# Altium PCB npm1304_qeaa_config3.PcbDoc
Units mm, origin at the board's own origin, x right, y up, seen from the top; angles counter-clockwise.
Board outline 16.75 x 14 mm, 4 copper layers (Top Layer, Mid-Layer 1, Mid-Layer 2, Bottom Layer), stack 1.592 mm thick; 8 components, 15 nets, 47 pads, 52 vias.
Unrouted connection lines stored in the file: 20.
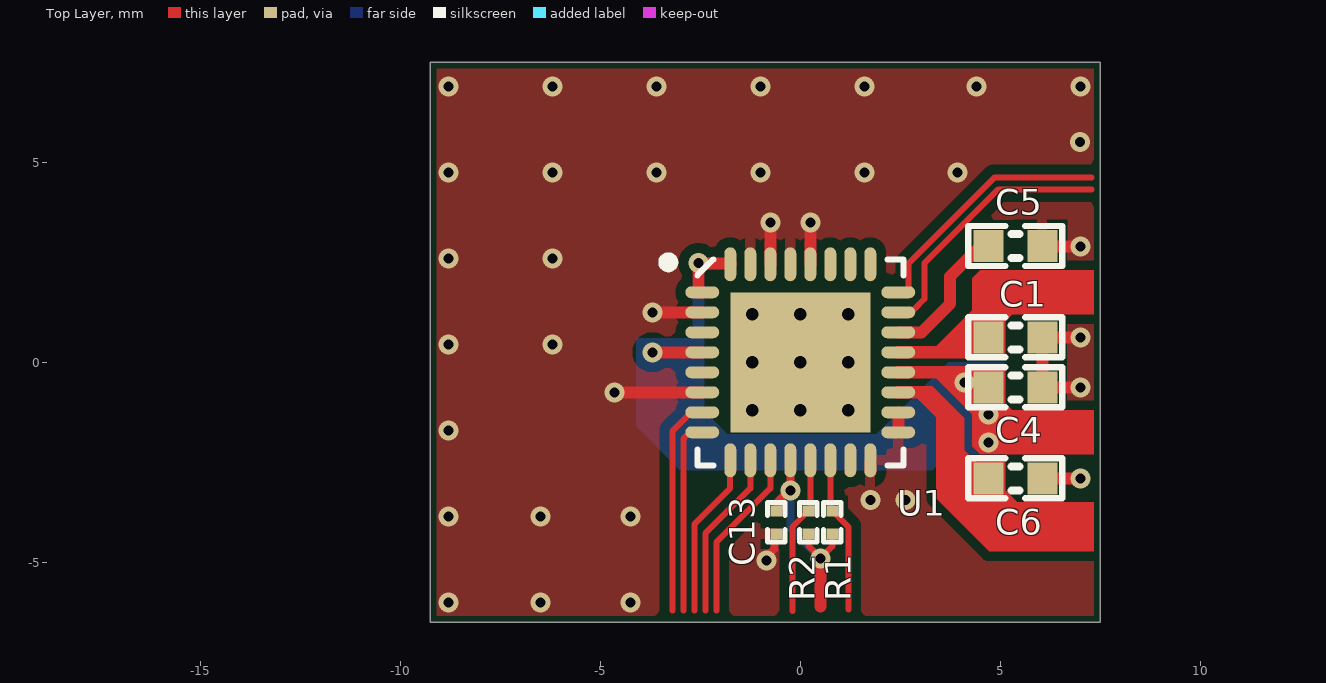
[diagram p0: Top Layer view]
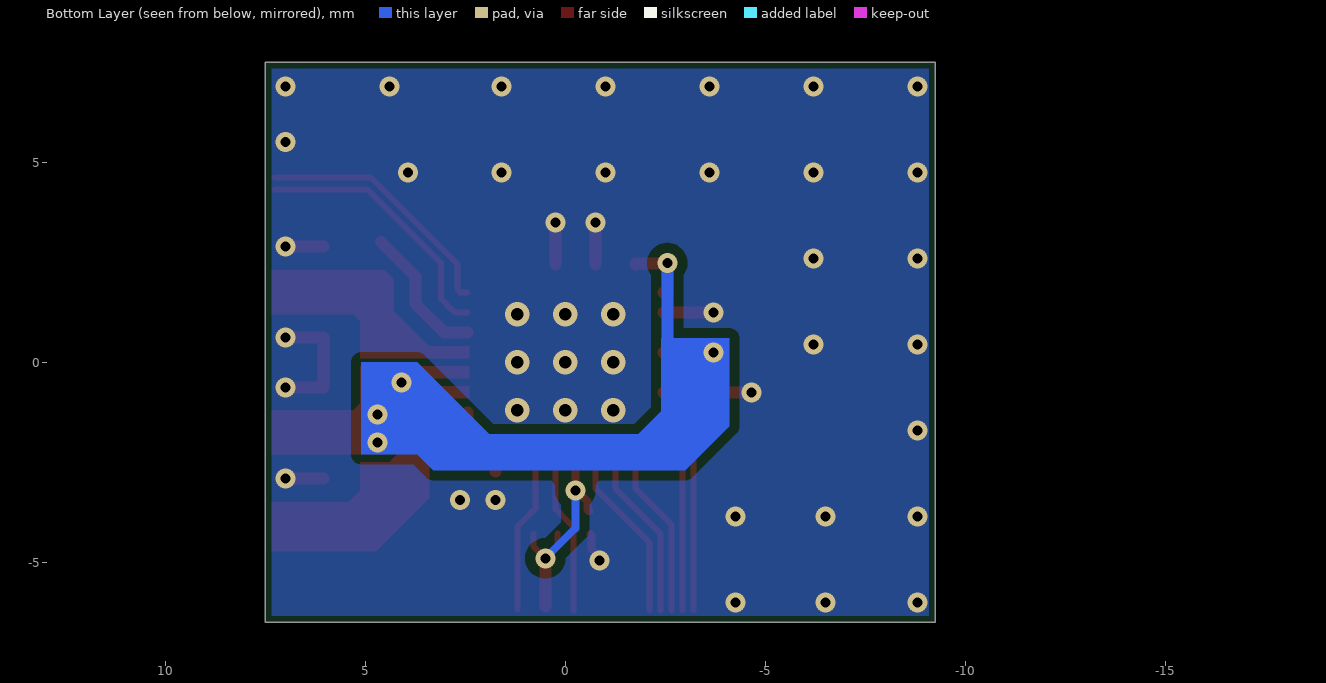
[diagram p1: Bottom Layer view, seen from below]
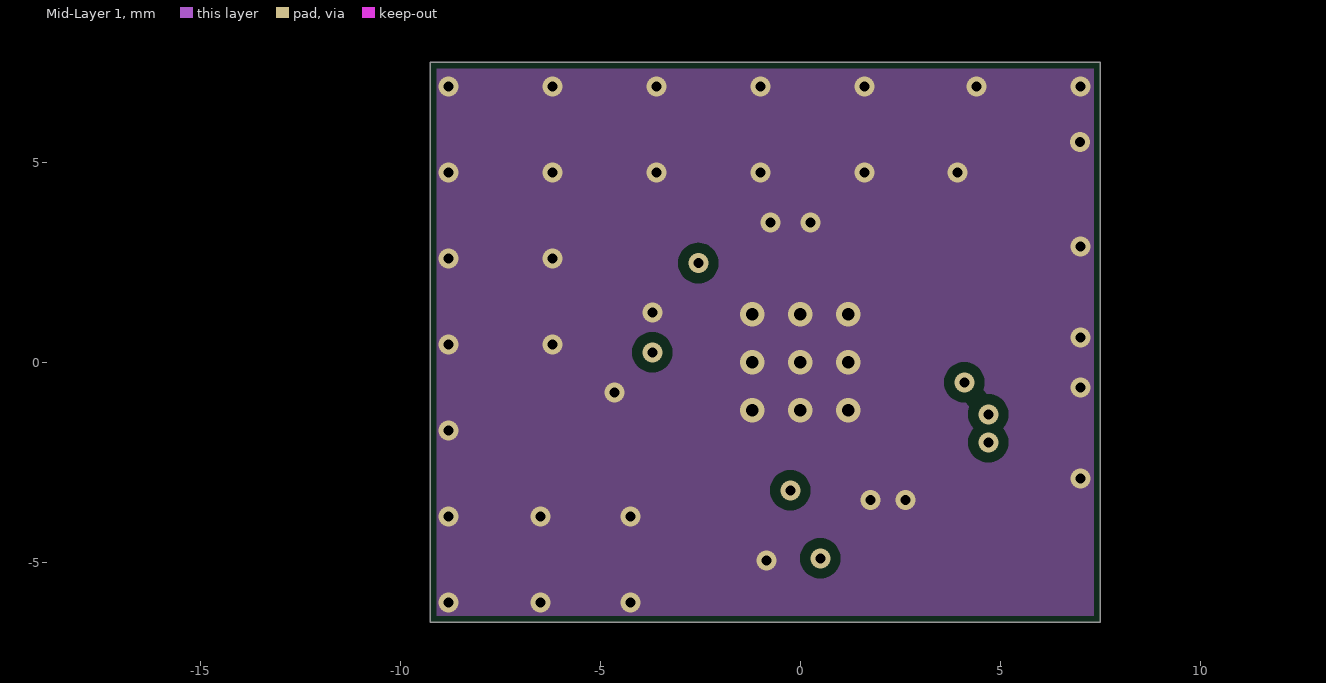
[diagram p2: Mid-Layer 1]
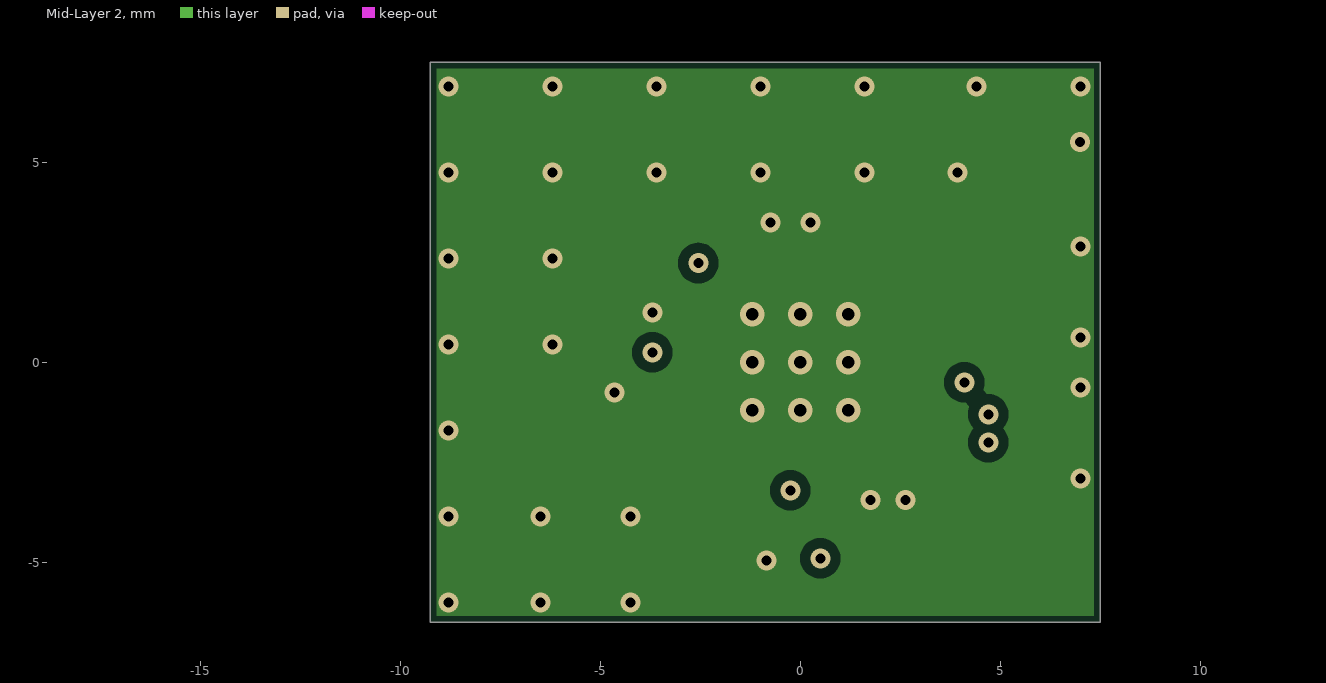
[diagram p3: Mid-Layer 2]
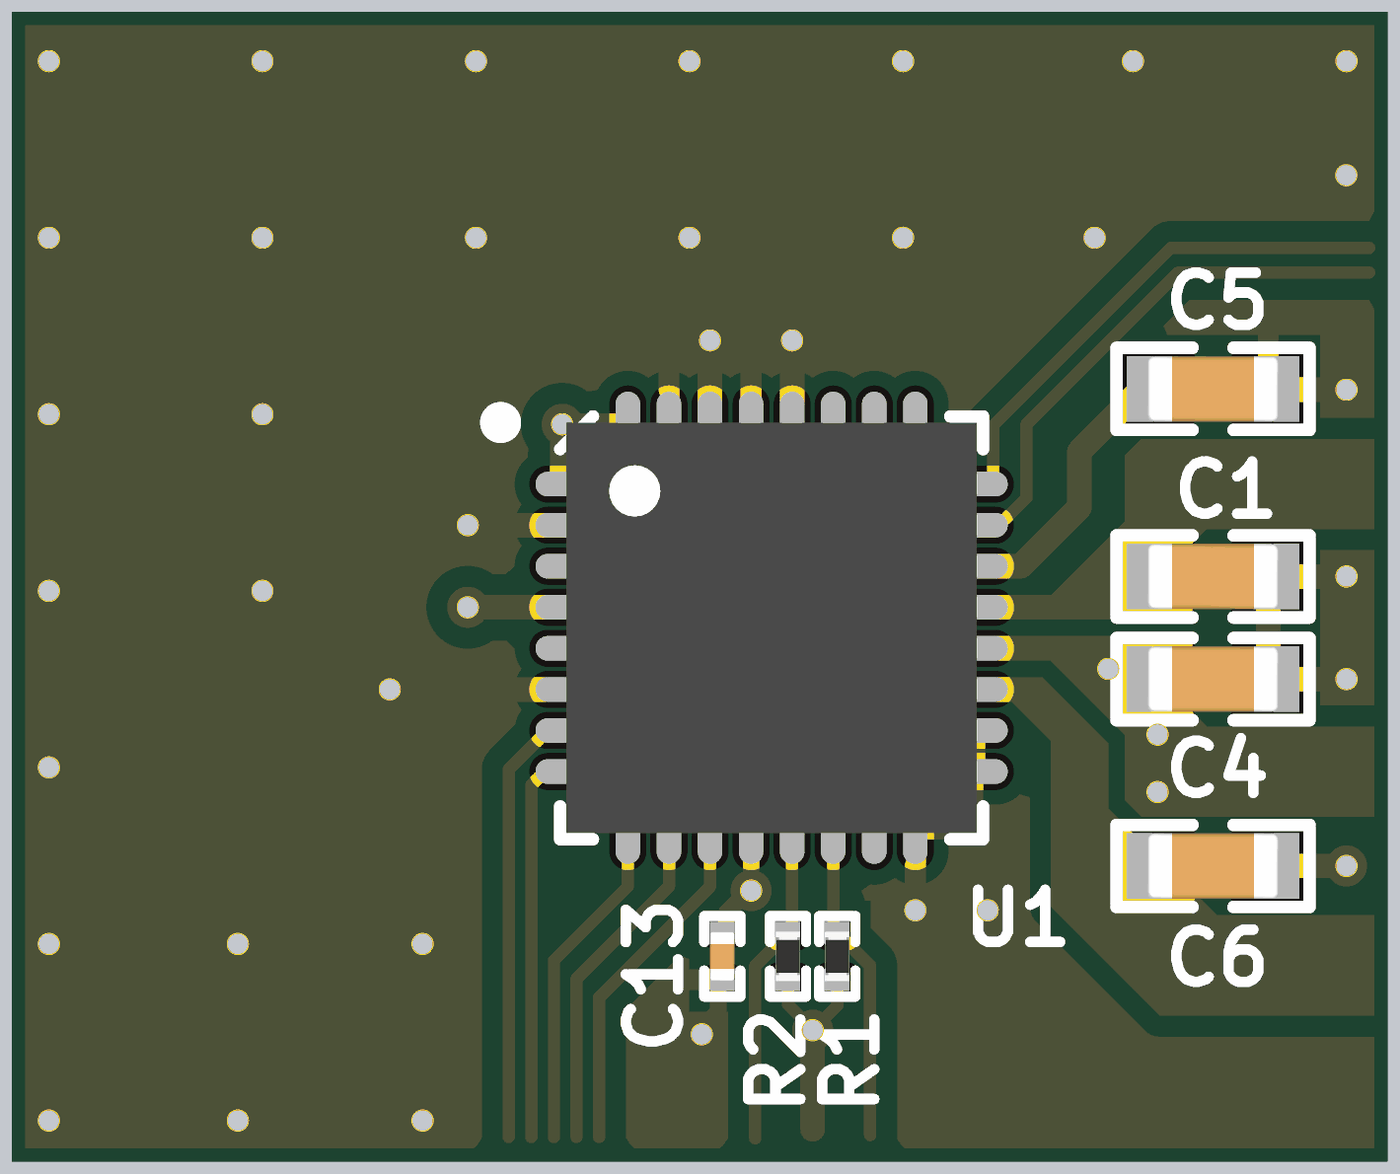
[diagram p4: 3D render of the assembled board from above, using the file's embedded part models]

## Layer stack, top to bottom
Top Solder: solder mask 0.0102, Solder Resist, Dk 3.5
Top Layer: signal copper 0.0356
Dielectric1: prepreg 0.075, FR-4, Dk 4.8
Mid-Layer 1: signal copper 0.0356
Dielectric2: core 1.3, FR-4, Dk 4.8
Mid-Layer 2: signal copper 0.0356
Dielectric 2: prepreg 0.075, FR-4, Dk 4.8
Bottom Layer: signal copper 0.0356
Bottom Solder: solder mask 0.0102, Solder Resist, Dk 3.5

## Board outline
-9.25,7.5 -9.25,-6.5 7.5,-6.5 7.5,7.5

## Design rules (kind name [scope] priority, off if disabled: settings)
BoardOutlineClearance [All] p1: gap=0.15 ignorepadtopadclearanceinfootprint=FALSE
Clearance Polygon_Clearance [(InNamedPolygon('Top_Layer-GND')) or (InNamedPolygon('Bottom_Layer-GND')) or (InNamedPolygon('Mid_Layer_1-GND')) or (InNamedPolygon('Mid_Layer_2-GND'))] p1: gap=0.254 ignorepadtopadclearanceinfootprint=FALSE except(0: Arc-Hole Track-Hole SMDPad-Hole THPad-Hole Via-Hole Fill-Hole Poly-Hole Region-Hole Text-Hole)
Clearance Clearance_Microvia [AsMM(ViaDiameter) = 0.3 vs AsMM(ViaDiameter) = 0.3] p2: gap=0.1 ignorepadtopadclearanceinfootprint=FALSE except(0: Arc-Hole Track-Hole)
Clearance ANT_Clerance [InNet('ANT')] p3: gap=0.127 ignorepadtopadclearanceinfootprint=FALSE except(0: Arc-Hole Track-Hole SMDPad-Hole THPad-Hole Via-Hole Fill-Hole Poly-Hole Region-Hole Text-Hole)
Clearance [All] p4: gap=0.125 ignorepadtopadclearanceinfootprint=FALSE
ComponentClearance [All] p1 off: gap=0.254 collisioncheckmode=3 verticalgap=0.254 showdistances=FALSE
DiffPairsRouting [All] p1: maxlimit=0.15 minlimit=0.127 mostfreqgap=0.15 toplayer_mingap=0.15 toplayer_minwidth=0.15 toplayer_maxwidth=0.15 toplayer_prefwidth=0.15 bottomlayer_mingap=0.15 bottomlayer_minwidth=0.15 bottomlayer_maxwidth=0.15 bottomlayer_prefwidth=0.15 impedanceprofiledriven=TRUE impedanceprofileid={DBD80B30-E3CF-4860-A6C7-45E32F93C55D} impedanceprofilevalue=90.000000 maxuncoupledlength=12.7
FabricationTestPointUsage TestPointUsage [All] p1: valid=0 allowmultiple=FALSE
FabricationTestpoint Testpoint [All] p1: side=3 testpointundercomponent=TRUE minsize=1.016 maxsize=2.54 preferedsize=1.524 minholesize=0 maxholesize=1.016 preferedholesize=0.813 testpointgrid=0.025 allowsidetop=TRUE allowsidebottom=TRUE usegrid=TRUE gridtolerance=0
Height [All] p1 off: minheight=0 maxheight=25.4 prefheight=12.7
HoleSize [All] p1: absolutevalues=TRUE maxlimit=5 minlimit=0.1 maxpercent=80.000 minpercent=20.000
MinimumAnnularRing [All] p1 off: minimumring=0.75
PolygonConnect PolygonConnect_GND [InNet('GND')] p1: thpad.connectstyle=Relief thpad.reliefconductorwidth=0.254 thpad.reliefentries=4 thpad.polygonreliefangle="90 Angle" thpad.airgapwidth=0.254 smdpad.connectstyle=Relief smdpad.reliefconductorwidth=0.254 smdpad.reliefentries=4 smdpad.polygonreliefangle="90 Angle" smdpad.airgapwidth=0.254 via.connectstyle=Direct via.reliefconductorwidth=0.254 via.reliefentries=4 via.polygonreliefangle="90 Angle" via.airgapwidth=0.254
PolygonConnect [All] p2: connectstyle=Direct reliefconductorwidth=0.254 reliefentries=4 polygonreliefangle="90 Angle" airgapwidth=0.254
RoutingVias [All] p1: holewidth=0.305 width=0.61 viastyle="Through Hole" minholewidth=0.305 minwidth=0.61 maxholewidth=0.711 maxwidth=1.27 useviatemplates=TRUE viatemplateguid#1={6F225C6A-EE86-4657-A426-C9A0349870D4} viatemplatename#1=v50h25m0mx0
ShortCircuit ShortCircuit_PVSS [InNet('PVSS1') or InNet('PVSS2') vs InNet('GND')] p1: allowed=TRUE
ShortCircuit [All] p2: allowed=FALSE
SilkToSolderMaskClearance SilkscreenOverComponentPads [IsPad] p1: minsilkscreentomaskgap=0.254 clearancetoexposedcopper=TRUE
SolderMaskExpansion SolderMaskExpansion_Vias [IsVia] p1: expansion=0.102 istentingtop=TRUE
SolderMaskExpansion [All] p2: expansion=0.076 istentingtop=FALSE
SupplyNets "Schematic Supply Nets_4" [InNet('VBAT')] p1: voltage=0.000
SupplyNets "Schematic Supply Nets_3" [InNet('GND')] p2: voltage=0.000
SupplyNets "Schematic Supply Nets_2" [InNet('VSYS')] p3: voltage=0.000
SupplyNets "Schematic Supply Nets_1" [InNet('VDDIO')] p4: voltage=0.000
SupplyNets "Schematic Supply Nets" [InNet('VBUSIN')] p5: voltage=0.000
UnRoutedNet [All] p1: checkbadconnections=TRUE
Width [All] p1: maxlimit=2 minlimit=0.12 preferedwidth=0.3
21 further rules are at their usual default settings.

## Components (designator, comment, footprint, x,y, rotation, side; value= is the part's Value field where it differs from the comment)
C1 "1.0µF" CAPC1608X06L 5.375,0.625 r180 top
C4 "10µF" CAPC1608X06L 5.375,-0.625 r180 top
C5 "1.0µF" CAPC1608X06L 5.375,2.91 r180 top
C6 "2.2µF" CAPC1608X06L 5.375,-2.9 r180 top
C13 "100nF" CAPC0603X03L_C -0.6,-4 r270 top
R1 "10k" RESC0603X03L_C 0.8,-4 r270 top
R2 "10k" RESC0603X03L_C 0.2,-4 r270 top
U1 "nPM1304-QEAA" Nordic_QFN50P500X500X90-33N 0,0 r0 top locked

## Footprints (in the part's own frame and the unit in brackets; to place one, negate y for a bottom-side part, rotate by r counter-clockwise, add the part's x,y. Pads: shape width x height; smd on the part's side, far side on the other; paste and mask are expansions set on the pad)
CAPC0603X03L_C [mm] "Chip Capacitor, 2-Leads, Body 0.6x0.3mm, IPC High Density"
  rect 0.27x0.3 smd mask+0.05: 1(-0.285,0) 2(0.285,0)
  silkscreen extent -0.49,-0.22 0.49,0.22, body extent -0.3,-0.15 0.3,0.15, height 0.3
CAPC1608X06L [mm] "Chip Capacitor, 2-Leads, Body 1.6x0.8mm, IPC High Density"
  rect 0.75x0.8 smd: 1(-0.675,0) 2(0.675,0)
  silkscreen extent -1.17,-0.5 1.17,0.5, body extent -0.8,-0.4 0.8,0.4, height 0.8
Nordic_QFN50P500X500X90-33N [mm] "QFN32 5x5x0.85mm, 0.5mm pitch - Medium Density"
  oval 0.85x0.3 smd mask+0.076: 1(-2.45,1.75) 2(-2.45,1.25) 3(-2.45,0.75) 4(-2.45,0.25) 5(-2.45,-0.25) 6(-2.45,-0.75) 7(-2.45,-1.25) 8(-2.45,-1.75) 17(2.45,-1.75) 18(2.45,-1.25) 19(2.45,-0.75) 20(2.45,-0.25) 21(2.45,0.25) 22(2.45,0.75) 23(2.45,1.25) 24(2.45,1.75)
  oval 0.3x0.85 smd mask+0.076: 9(-1.75,-2.45) 10(-1.25,-2.45) 11(-0.75,-2.45) 12(-0.25,-2.45) 13(0.25,-2.45) 14(0.75,-2.45) 15(1.25,-2.45) 16(1.75,-2.45) 25(1.75,2.45) 26(1.25,2.45) 27(0.75,2.45) 28(0.25,2.45) 29(-0.25,2.45) 30(-0.75,2.45) 31(-1.25,2.45) 32(-1.75,2.45)
  rect 3.5x3.5 smd: 33(0,0)
  silkscreen extent -3.42,-2.57 2.57,2.62, body extent -2.5,-2.5 2.5,2.5, height 0.9
RESC0603X03L_C [mm] "Chip Resistor, 2-Leads, Body 0.6x0.3mm, IPC High Density"
  rect 0.27x0.3 smd: 1(-0.285,0) 2(0.285,0)
  silkscreen extent -0.49,-0.22 0.49,0.22, body extent -0.3,-0.15 0.3,0.15, height 0.23

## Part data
C1: library part C0603-1µ0-25V-X5R, "Capacitor, X5R, ±10%, 25V", Manufacturer=N.A., Part number NEMS=100200687
C4: library part C0603-10µ, "Capacitor, X5R, ±20%", Manufacturer=N.A., Part number IPS=00000007785, Part number NEMS=100200275
C5: library part C0603-1µ0-10V-X5R, "Capacitor, Ceramic, 1.0µF 10V X5R 0603,±10%", Manufacturer=N.A., Part number NEMS=100200528
C6: library part C0603-2.2µ-16V-X7R, "Capacitor, Ceramic, X7R, ±10%, 16V", Manufacturer="Taiyo Yuden", Manufacturer Part Number=EMK107BB7225KA-T, Part number IPS=N.A., Part number NEMS=100200439, Supplier Part Number 1=587-5835-2-ND
C13: library part C0201-100n, "Capacitor, X5R, ±10%, 100nF, 16V", Manufacturer=N.A., Part number IPS="00000001248, 00000002505", Part number NEMS=100200078, Part number Norautron=262071862
R1 R2: library part R0201-10k, "Resistor, ±1%, 0.05W", Manufacturer=N.A., Part number IPS=00000001255, Part number NEMS=100100065, Part number Norautron=26107101
U1: "Li-Ion/Li-Polymer USB-C battery charger with high efficiency buck regulators, LDOs or load switches, LED drivers, TWI and VBUSOUT", Manufacturer="Nordic Semiconductor", Part number IPS=N.A., Part number NEMS=102000396

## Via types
v1: diameter 0.5, hole 0.25, Top Layer to Bottom Layer, tented both sides, 43 vias
v2: diameter 0.61, hole 0.305, Top Layer to Bottom Layer, tented both sides, 9 vias

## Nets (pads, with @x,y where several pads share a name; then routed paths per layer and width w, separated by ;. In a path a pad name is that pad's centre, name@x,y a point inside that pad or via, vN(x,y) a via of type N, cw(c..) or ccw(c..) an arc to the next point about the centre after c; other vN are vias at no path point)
CC1: U1.23 | length 6.6
  Top Layer w0.15: U1.23 2.766,1.25 2.841,1.325 2.846,1.325 3.104,1.583 3.104,2.478 4.951,4.325 7.275,4.325
CC2: U1.24 | length 6.4
  Top Layer w0.15: U1.24 2.631,1.75 2.7,1.819 2.7,2.463 4.862,4.625 7.275,4.625
GND: C1.1 C4.1 C5.1 C6.1 C13.2 U1.2 U1.6 U1.16 U1.17 U1.18 U1.28 U1.29 U1.30 U1.31 U1.33 | length 11.3
  Top Layer w0.2: v1(-0.85,-4.95) -0.85,-4.869 -0.65,-4.669 -0.65,-4.315 C13.2@-0.627,-4.292
  Top Layer w0.3: v1(-4.65,-0.75) U1.6 ; v1(-3.7,1.25) U1.2 ; U1.30 v1(-0.75,3.5) ; U1.28 v1(0.25,3.5) ; U1.16@1.75,-2.725 U1.16 ; U1.17 U1.18 ; C6.1 v1@6.9,-2.9 ; C4.1 C1.1 v1@6.8,0.625 ; C5.1@6.05,2.9 v1@6.8,2.9 ; C4.1@6.125,-0.625 v1@6.8,-0.625
  other v1: -8.8,-6 -6.5,-6 -4.25,-6 -8.8,-3.85 -6.5,-3.85 -4.25,-3.85 1.75,-3.44 2.631,-3.44 7,-2.9 -8.8,-1.7 7,-0.625 -8.8,0.45 -6.2,0.45 7,0.625 -8.8,2.6 -6.2,2.6 7,2.9 -8.8,4.75 -6.2,4.75 -3.6,4.75 -1,4.75 1.6,4.75 3.933,4.75 6.997,5.512 -8.8,6.9 -6.2,6.9 -3.6,6.9 -1,6.9 1.6,6.9 4.4,6.9 7,6.9
  other v2: -1.2,-1.2 0,-1.2 1.2,-1.2 -1.2,0 0,0 1.2,0 -1.2,1.2 0,1.2 1.2,1.2
GPIO0: U1.7 | length 5.4
  Top Layer w0.15: -3.2,-6.2 -3.2,-1.725 -2.725,-1.25 U1.7
GPIO1: U1.8 | length 4.8
  Top Layer w0.15: -2.925,-6.2 -2.925,-1.913 -2.762,-1.75 U1.8
GPIO2: U1.9 | length 4.1
  Top Layer w0.15: -2.65,-6.2 -2.65,-4.05 -1.753,-3.153 -1.753,-2.453 U1.9
GPIO3: U1.10 | length 4.2
  Top Layer w0.15: -2.375,-6.2 -2.375,-4.275 -1.25,-3.15 U1.10
GPIO4: U1.11 | length 4.3
  Top Layer w0.15: -2.1,-6.2 -2.1,-4.5 -0.75,-3.15 U1.11
NetC5_2: C5.2 U1.22 | length 3.5
  Top Layer w0.3: U1.22 3.033,0.75 3.748,1.465 3.748,2.148 C5.2@4.613,3.013
SCL: R1.1 U1.14 | length 3.9
  Top Layer w0.15: U1.14 0.75,-3.665 R1.1 0.815,-3.715 0.875,-3.775 0.875,-3.79 1.2,-4.115 1.2,-6.178
SDA: R2.1 U1.13 | length 4
  Top Layer w0.15: -0.2,-6.216 -0.2,-4.117 0.125,-3.792 0.125,-3.775 0.22,-3.68 0.25,-3.68 U1.13
VBAT: C6.2 U1.19
VBUSIN: C1.2 U1.21
VDDIO: C13.1 R1.2 R2.2 U1.12 | length 6.2
  Top Layer w0.15: R2.2 0.2,-4.586 v1@0.45,-4.836 ; v1@0.5,-4.786 v1(0.5,-4.9) 0.8,-4.6 R1.2
  Top Layer w0.2: C13.1 -0.585,-3.715 -0.55,-3.68 -0.55,-3.467 -0.283,-3.2 v1(-0.25,-3.2) -0.25,-3 U1.12
  Top Layer w0.3: 0.5,-6.106 v1(0.5,-4.9)
  Bottom Layer w0.2: v1(-0.25,-3.2) -0.25,-4.15 v1(0.5,-4.9)
VSYS: C4.2 U1.1 U1.4 U1.20 U1.32 | length 6.1
  Top Layer w0.3: v1(-3.7,0.25) U1.4 ; U1.1 -2.55,1.75 v1(-2.55,2.478) -2.536,2.464 -1.75,2.464 U1.32
  Bottom Layer w0.3: v1(-3.7,0.25) -2.875,0.25 -2.55,0.575 v1(-2.55,2.478)
  other v1: 4.7,-2 4.7,-1.3 4.1,-0.5
pads on no net: U1.3 U1.5 U1.15 U1.25 U1.26 U1.27

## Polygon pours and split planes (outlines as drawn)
GND on Mid-Layer 1 "Mid_Layer_1-GND" (solid, remove dead copper, pour order 24): -9.25,-6.5 7.5,-6.5 7.5,7.5 -9.25,7.5
GND on Mid-Layer 2 "Mid_Layer_2-GND" (solid, remove dead copper, pour order 25): -9.25,-6.5 7.5,-6.5 7.5,7.5 -9.25,7.5
GND on Bottom Layer "Bottom_Layer-GND" (solid, remove dead copper, pour order 26): -9.25,-6.5 7.5,-6.5 7.5,7.5 -9.25,7.5
GND on Top Layer "Top_Layer-GND" (solid, remove dead copper, pour order 21): -9.25,-6.5 7.5,-6.5 7.5,7.5 -9.25,7.5

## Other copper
Top Layer:
  region net VBUSIN: 5.125,0.1 5.125,1.025 5.3,1.2 7.338,1.2 7.338,2.3 4.5,2.3 4.3,2.1 4.3,1.3 3.4,0.4 2.4,0.4 2.4,0.1
  region net VSYS: 5.125,-0.1 5.125,-1.025 5.3,-1.2 7.338,-1.2 7.338,-2.3 4.5,-2.3 4.3,-2.1 4.3,-1.3 3.4,-0.4 2.4,-0.4 2.4,-0.1
  region net VBAT: 2.4,-0.9 2.925,-0.9 3.4,-1.375 3.4,-3.4 4.725,-4.725 7.338,-4.725 7.338,-3.5 5.425,-3.5 5.125,-3.2 5.125,-2.5 4.4,-2.5 4.1,-2.2 4.1,-1.4 3.3,-0.6 2.4,-0.6
  pour cut-out: -1.85,1.85 1.85,1.85 1.85,-1.85 -1.85,-1.85
  pour cut-out: -17.9,1.7 -17.9,-3.2
  pour cut-out: 7.375,0.45 7.375,-0.41
Mid-Layer 1:
  pour cut-out: 11.025,5.525 12.025,5.525
Bottom Layer:
  region net VSYS: -4.1,0.6 -4.1,-1.6 -3,-2.7 3.3,-2.7 3.7,-2.3 5.1,-2.3 5.1,0 3.7,0 1.9,-1.8 -1.825,-1.8 -2.4,-1.225 -2.4,0.6

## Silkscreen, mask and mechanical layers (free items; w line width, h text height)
Board Outline:
  the board outline again, w0.2

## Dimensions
7.5,-6.5 to 7.5,7.5 on Dimension
-9.25,-6.5 to 7.5,-6.5 on Dimension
